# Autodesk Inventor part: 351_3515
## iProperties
Author: tomm
Created: 2002-01
Part Number: 351_3515
Document SubType Name: Modeling
Designer: tomm
Material: Steel, Mild
Control State: 0
Master: False
Checked Out: False
Last Check In Date: 2002-01-29
PropertySet Name: Design Tracking Control
Last Check In By: tomm
Shininess: 86.0
PropertySet Name: _Private Model Information
Density: 7.86
Volume: 8.098471086169653
Area: 42.02648407358389
PropertySet Name: Model Information
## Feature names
1. Base1
2. Extrusion1
3. Fillet1
